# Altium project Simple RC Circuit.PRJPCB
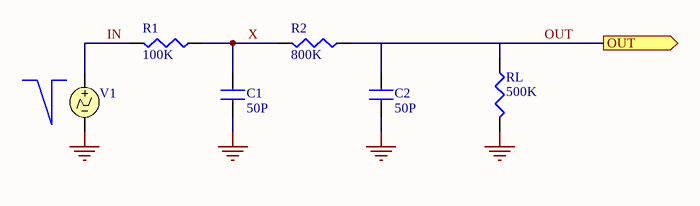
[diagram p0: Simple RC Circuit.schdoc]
1 sheet, 6 parts. Net scope: flat (ports and power ports of the same name join across sheets).

## Sheet Simple RC Circuit.schdoc: Simple RC Circuit
size A4; Organization: Altium Limited; Address1: L3, 12a Rodborough Rd; Address2: Frenchs Forest; Address3: NSW; Address4: Australia 2086; DocumentNumber: 1; SheetNumber: 1; SheetTotal: 1

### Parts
C1  50P
C2  50P
R1  100K
R2  800K
RL  500K
V1  VPWL  (value not drawn)

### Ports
OUT (out)

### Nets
GND: C1.2 C2.2 RL.1(TOP) V1.2
IN: R1.1(TOP) V1.1
OUT: C2.1 R2.2(BOT) RL.2(BOT) ; port OUT
X: C1.1 R1.2(BOT) R2.1(TOP)

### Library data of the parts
C1 C2 = CAP: Capacitor
R1 R2 RL = RES: Resistor
V1 = VPWL: Piecewise Linear Voltage Source; Time-Value Pairs: 0 5 5U 5 12U 0 50U 5 60U 5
